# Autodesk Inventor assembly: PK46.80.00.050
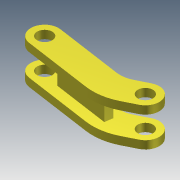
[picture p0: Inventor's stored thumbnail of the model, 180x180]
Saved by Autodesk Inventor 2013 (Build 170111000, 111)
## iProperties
Created: 2005-05
Part Number: PK46.80.00.050
Document SubType Name: Assembly
Designer: salex
Manufacturer: Standard
Standards Organization: Custom
Author: salex
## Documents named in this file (3)
- D:\FrontLoaderVault\Data\Assy, Chassis, Front\PK46.80.00.050.iam
- D:\FrontLoaderVault\Data\Assy, Chassis, Front\PK46.80.00.023.ipt
- D:\FrontLoaderVault\Data\Assy, Chassis, Front\PK46.80.00.024.ipt
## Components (3 placed, 2 different names)
1. PK46.80.00.023:1 — Mate:1, Mate:3, Mate:4, Flush:1
2. PK46.80.00.023:2 — Mate:2, Mate:3, Mate:4, Mate:5
3. PK46.80.00.024:1 — Mate:1, Mate:2, Mate:5, Flush:1
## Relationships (6: Mate 5, Flush 1)
- Mate:1: PK46.80.00.023:1 ↔ PK46.80.00.024:1
- Mate:2: PK46.80.00.023:2 ↔ PK46.80.00.024:1
- Mate:3: PK46.80.00.023:1 ↔ PK46.80.00.023:2
- Mate:4: PK46.80.00.023:1 ↔ PK46.80.00.023:2
- Mate:5: PK46.80.00.023:2 ↔ PK46.80.00.024:1
- Flush:1: PK46.80.00.023:1 ↔ PK46.80.00.024:1
